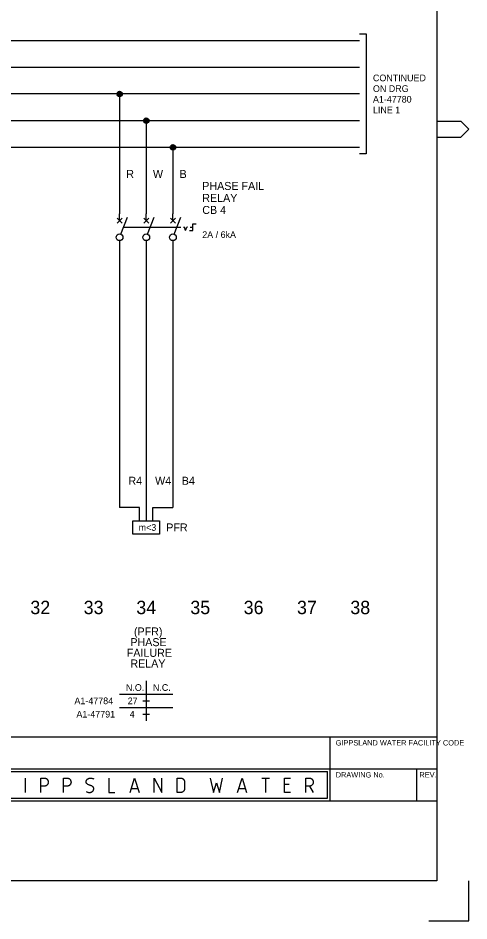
# Model space of a CAD drawing. Extents: x 0 to 841, y 0 to 594.
# Drawn here: x 671.9 to 841, y 0 to 338.4 of the extents above; entities that cross this region are included whole.
import ezdxf

# ---------------------------------------------------------------- set-up
doc = ezdxf.new("R2010")
doc.units = 0
for name, color, linetype in [('A1BORDER', 7, 'Continuous'), ('Level 1', 7, 'Continuous'), ('Level 10', 7, 'Continuous'), ('Level 2', 7, 'Continuous')]:
    doc.layers.add(name, color=color, linetype=linetype)

msp = doc.modelspace()

# ---------------------------------------------------------------- linework, layer by layer
at = {"layer": 'A1BORDER'}
for p, q in [((829, 581), (829, 15)), ((829, 299.76), (838, 299.76)), ((838, 299.76), (841, 296.76)), ((838, 293.76), (841, 296.76)), ((829, 293.76), (838, 293.76)), ((592.5, 69), (829, 69)), ((789, 45), (789, 69)), ((28, 57), (829, 57)), ((637, 56), (788, 56)), ((788, 46), (788, 56)), ((821.5, 45), (821.5, 57)), ((663, 46), (788, 46)), ((664, 45), (829, 45)), ((829, 15), (28, 15)), ((829, 15), (829, 15)), ((841, 0), (841, 15)), ((826, 0), (841, 0))]:
    msp.add_line(p, q, dxfattribs=at)
for points in [[(674.74, 48.16), (674.74, 53.54)], [(680.42, 48.16), (680.42, 53.54), (681.84, 53.54), (681.96, 53.54), (682.08, 53.52), (682.2, 53.49), (682.32, 53.45), (682.43, 53.4), (682.54, 53.34), (682.65, 53.27), (682.74, 53.19), (682.84, 53.1), (682.92, 53), (682.99, 52.9), (683.06, 52.79), (683.12, 52.67), (683.17, 52.56), (683.21, 52.43), (683.23, 52.31), (683.25, 52.18), (683.26, 52.05), (683.25, 51.91), (683.23, 51.78), (683.21, 51.66), (683.17, 51.53), (683.12, 51.42), (683.06, 51.3), (682.99, 51.19), (682.92, 51.09), (682.84, 50.99), (682.74, 50.9), (682.65, 50.82), (682.54, 50.75), (682.43, 50.69), (682.32, 50.64), (682.2, 50.6), (682.08, 50.57), (681.96, 50.55), (681.84, 50.55), (680.42, 50.55)], [(688.93, 48.16), (688.93, 53.54), (690.35, 53.54), (690.47, 53.54), (690.59, 53.52), (690.71, 53.49), (690.83, 53.45), (690.94, 53.4), (691.05, 53.34), (691.16, 53.27), (691.26, 53.19), (691.35, 53.1), (691.43, 53), (691.51, 52.9), (691.57, 52.79), (691.63, 52.67), (691.68, 52.56), (691.72, 52.43), (691.75, 52.31), (691.76, 52.18), (691.77, 52.05), (691.76, 51.91), (691.75, 51.78), (691.72, 51.66), (691.68, 51.53), (691.63, 51.42), (691.57, 51.3), (691.51, 51.19), (691.43, 51.09), (691.35, 50.99), (691.26, 50.9), (691.16, 50.82), (691.05, 50.75), (690.94, 50.69), (690.83, 50.64), (690.71, 50.6), (690.59, 50.57), (690.47, 50.55), (690.35, 50.55), (688.93, 50.55)], [(697.45, 48.46), (697.67, 48.36), (697.9, 48.27), (698.12, 48.21), (698.36, 48.17), (698.6, 48.16), (698.84, 48.16), (698.87, 48.16), (699.03, 48.18), (699.18, 48.21), (699.33, 48.26), (699.48, 48.32), (699.62, 48.4), (699.72, 48.46), (699.81, 48.53), (699.9, 48.61), (699.98, 48.69), (700.05, 48.78), (700.11, 48.88), (700.17, 48.99), (700.22, 49.09), (700.25, 49.21), (700.28, 49.32), (700.29, 49.36), (700.3, 49.44), (700.3, 49.52), (700.3, 49.61), (700.29, 49.69), (700.27, 49.77), (700.25, 49.86), (700.22, 49.93), (700.18, 50.01), (700.14, 50.09), (700.09, 50.15), (700.04, 50.21), (700.01, 50.25), (699.85, 50.39), (699.69, 50.51), (699.52, 50.61), (699.34, 50.7), (699.15, 50.78), (698.95, 50.83), (698.87, 50.85), (698.68, 50.9), (698.49, 50.96), (698.3, 51.04), (698.12, 51.14), (697.96, 51.26), (697.8, 51.39), (697.73, 51.45), (697.67, 51.51), (697.62, 51.57), (697.58, 51.64), (697.53, 51.71), (697.5, 51.79), (697.47, 51.87), (697.46, 51.95), (697.44, 52.04), (697.43, 52.12), (697.43, 52.21), (697.44, 52.29), (697.45, 52.35), (697.47, 52.46), (697.51, 52.58), (697.55, 52.69), (697.61, 52.79), (697.67, 52.89), (697.74, 52.99), (697.82, 53.07), (697.9, 53.15), (697.99, 53.23), (698.02, 53.24), (698.15, 53.33), (698.3, 53.4), (698.44, 53.45), (698.6, 53.5), (698.75, 53.52), (698.87, 53.54), (699.11, 53.55), (699.35, 53.53), (699.58, 53.49), (699.82, 53.43), (700.04, 53.35), (700.27, 53.25)], [(705.96, 53.54), (705.96, 48.16), (708.23, 48.16)], [(713.91, 48.16), (715.61, 53.54), (717.32, 48.16)], [(722.99, 48.16), (722.99, 53.54), (725.83, 48.16), (725.83, 53.54)], [(731.52, 48.16), (731.52, 53.54), (732.94, 53.54), (733.06, 53.54), (733.18, 53.52), (733.3, 53.49), (733.42, 53.45), (733.53, 53.4), (733.64, 53.34), (733.75, 53.27), (733.84, 53.19), (733.94, 53.1), (734.02, 53), (734.09, 52.9), (734.16, 52.79), (734.22, 52.67), (734.27, 52.56), (734.31, 52.43), (734.33, 52.31), (734.35, 52.18), (734.36, 52.05), (734.36, 49.66), (734.35, 49.52), (734.33, 49.39), (734.31, 49.27), (734.27, 49.14), (734.22, 49.02), (734.16, 48.91), (734.09, 48.8), (734.02, 48.7), (733.94, 48.6), (733.84, 48.51), (733.75, 48.43), (733.64, 48.36), (733.53, 48.3), (733.42, 48.25), (733.3, 48.21), (733.18, 48.18), (733.06, 48.16), (732.94, 48.16), (731.52, 48.16)], [(744.01, 53.54), (745.14, 48.16), (746.28, 51.75), (747.41, 48.16), (748.55, 53.54)], [(754.22, 48.16), (755.92, 53.54), (757.63, 48.16)], [(763.31, 53.54), (766.15, 53.54)], [(764.73, 53.54), (764.73, 48.16)], [(774.09, 48.16), (771.82, 48.16), (771.82, 53.54), (774.09, 53.54)], [(773.53, 51.15), (771.82, 51.15)], [(779.78, 48.16), (779.78, 53.54), (781.2, 53.54), (781.32, 53.54), (781.44, 53.52), (781.56, 53.49), (781.68, 53.45), (781.79, 53.4), (781.9, 53.34), (782.01, 53.27), (782.1, 53.19), (782.2, 53.1), (782.28, 53), (782.35, 52.9), (782.42, 52.79), (782.48, 52.67), (782.53, 52.56), (782.56, 52.43), (782.59, 52.31), (782.61, 52.18), (782.61, 52.05), (782.61, 51.91), (782.59, 51.78), (782.56, 51.66), (782.53, 51.53), (782.48, 51.42), (782.42, 51.3), (782.35, 51.19), (782.28, 51.09), (782.2, 50.99), (782.1, 50.9), (782.01, 50.82), (781.9, 50.75), (781.79, 50.69), (781.68, 50.64), (781.56, 50.6), (781.44, 50.57), (781.32, 50.55), (781.2, 50.55), (779.78, 50.55)], [(714.48, 49.66), (716.75, 49.66)], [(754.79, 49.66), (757.06, 49.66)], [(781.2, 50.55), (782.61, 48.16)]]:
    msp.add_lwpolyline(points, dxfattribs=at)
at = {"layer": 'Level 1'}
for p, q in [((50, 330), (800, 330)), ((50, 320), (800, 320)), ((800, 310), (50, 310)), ((709.99, 310), (709.99, 265)), ((50, 300), (800, 300)), ((719.99, 300), (719.99, 265)), ((50, 290), (800, 290)), ((729.99, 290), (729.99, 265)), ((709.99, 262.5), (709.99, 265)), ((719.99, 262.5), (719.99, 265)), ((729.99, 262.5), (729.99, 265)), ((709.05, 263.44), (710.93, 261.56)), ((710.93, 263.44), (709.05, 261.56)), ((710.45, 257.41), (712.99, 263.75)), ((719.05, 263.44), (720.93, 261.56)), ((720.93, 263.44), (719.05, 261.56)), ((720.45, 257.41), (722.99, 263.75)), ((729.05, 263.44), (730.93, 261.56)), ((730.93, 263.44), (729.05, 261.56)), ((730.45, 257.41), (732.99, 263.75)), ((711.49, 260), (731.49, 260)), ((709.99, 255), (709.99, 155)), ((719.99, 255), (719.99, 150)), ((729.99, 255), (729.99, 155)), ((717.49, 155), (709.99, 155)), ((717.49, 150), (717.49, 155)), ((722.49, 150), (722.49, 155)), ((722.49, 155), (729.99, 155)), ((720, 90), (720, 75)), ((710, 85), (730, 85)), ((718.75, 82.5), (721.25, 82.5)), ((710, 80), (730, 80)), ((718.75, 77.5), (721.25, 77.5))]:
    msp.add_line(p, q, dxfattribs=at)
msp.add_lwpolyline([(800, 332.5), (802.5, 332.5), (802.5, 287.5), (800, 287.5)], dxfattribs=at)
for centre in [(709.99, 256.25), (719.99, 256.25), (729.99, 256.25)]:
    msp.add_circle(centre, 1.25, dxfattribs=at)
at = {"layer": 'Level 10'}
for p, q in [((709, 310.1), (710.98, 310.1)), ((709.01, 309.8), (710.97, 309.8)), ((709.07, 310.4), (710.91, 310.4)), ((709.12, 309.5), (710.86, 309.5)), ((709.28, 310.7), (710.7, 310.7)), ((709.39, 309.2), (710.59, 309.2)), ((709.99, 311), (709.99, 311)), ((719, 300.1), (720.98, 300.1)), ((719.01, 299.8), (720.97, 299.8)), ((719.07, 300.4), (720.91, 300.4)), ((719.12, 299.5), (720.86, 299.5)), ((719.28, 300.7), (720.7, 300.7)), ((719.39, 299.2), (720.59, 299.2)), ((719.99, 301), (719.99, 301)), ((729, 290.1), (730.98, 290.1)), ((729.01, 289.8), (730.97, 289.8)), ((729.07, 290.4), (730.91, 290.4)), ((729.12, 289.5), (730.86, 289.5)), ((729.28, 290.7), (730.7, 290.7)), ((729.39, 289.2), (730.59, 289.2)), ((729.99, 291), (729.99, 291)), ((737.49, 258.75), (737.49, 261.25)), ((737.49, 261.25), (738.74, 261.25)), ((731.49, 260), (732.99, 260)), ((733.99, 260), (734.32, 260)), ((734.74, 258.75), (734.32, 260)), ((734.74, 258.75), (735.16, 260)), ((735.49, 260), (735.16, 260)), ((736.24, 258.75), (737.49, 258.75)), ((736.49, 260), (737.49, 260))]:
    msp.add_line(p, q, dxfattribs=at)
for centre in [(709.99, 310), (719.99, 300), (729.99, 290)]:
    msp.add_circle(centre, 1, dxfattribs=at)
at = {"layer": 'Level 2'}
msp.add_lwpolyline([(714.99, 145), (714.99, 150), (724.99, 150), (724.99, 145)], close=True, dxfattribs=at)

# ---------------------------------------------------------------- texts
at = {"layer": 'A1BORDER'}
for s, p in [('GIPPSLAND WATER FACILITY CODE', (791.03, 65.77)), ('DRAWING No.', (791.03, 53.77)), ('REV.', (822.43, 53.77))]:
    msp.add_text(s, height=2, dxfattribs=at).set_placement(p)
at = {"layer": 'Level 1'}
for s, height, p in [('CONTINUED', 2.5, (805, 314.75)), ('ON DRG', 2.5, (805, 310.75)), ('A1-47780', 2.5, (805, 306.75)), ('LINE 1', 2.5, (805, 302.75)), ('R', 3, (712.49, 278.5)), ('W', 3, (722.49, 278.5)), ('B', 3, (732.49, 278.5)), ('PHASE FAIL', 3, (740.99, 274.01)), ('RELAY', 3, (740.99, 269.51)), ('CB 4', 3, (740.99, 265.01)), ('2A / 6kA', 2.5, (740.99, 256)), ('R4', 3, (713.3, 163.5)), ('W4', 3, (723.3, 163.5)), ('B4', 3, (733.3, 163.5)), ('PFR', 3, (727.49, 146)), ('m<3', 2.5, (717.13, 146.25)), ('32', 5, (676.52, 115)), ('33', 5, (696.52, 115)), ('34', 5, (716.26, 115)), ('35', 5, (736.52, 115)), ('36', 5, (756.52, 115)), ('37', 5, (776.52, 115)), ('38', 5, (796.52, 115)), ('(PFR)', 3, (715.37, 107)), ('PHASE', 3, (714.02, 103)), ('FAILURE', 3, (712.68, 99)), ('RELAY', 3, (714.02, 95)), ('N.O.', 2.5, (712.36, 86.25)), ('N.C.', 2.5, (722.48, 86.25)), ('A1-47784', 2.5, (693.06, 81.25)), ('27', 2.5, (713.02, 81.25)), ('A1-47791', 2.5, (693.8, 76.25)), ('4', 2.5, (713.77, 76.25))]:
    msp.add_text(s, height=height, dxfattribs=at).set_placement(p)

doc.saveas('drawing.dxf')
